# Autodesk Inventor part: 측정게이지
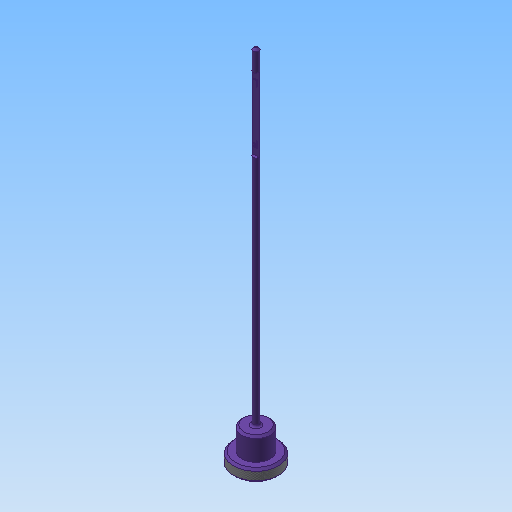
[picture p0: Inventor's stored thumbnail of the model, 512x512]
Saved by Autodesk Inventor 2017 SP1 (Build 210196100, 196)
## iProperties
Created: 2017-05
Part Number: 측정게이지
Material: 스테인리스강
Document SubType Name: Modeling
Designer: mduedu
Density: 8.08 g/cm^3
Mass: 39.5088 g
Surface Area: 29.9761 cm^2
Volume: 4.8897 cm^3
Appearance: 보라색
Author: mduedu
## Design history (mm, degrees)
sketch "스케치1"
  geometry: C1 r 11 at (0, 0); 1 further point
  constraints: 1 centre point, 1 coincident
  dimensions: "d0" = 22 diameter of C1
extrude "돌출1" new body sketch "스케치1" distance "d2" = 6; taper "d3" = 0 deg
sketch "스케치2"
  geometry: C1 r 7 at (0, 0); 1 further point
  constraints: 1 centre point, 1 coincident
  dimensions: "d4" = 14 diameter of C1
extrude "돌출2" join sketch "스케치2" distance "d5" = 11; taper "d6" = 0 deg
sketch "스케치3"
  geometry: C1 r 1.5 at (0, 0); 1 further point
  constraints: 1 centre point, 1 coincident
  dimensions: "d7" = 3 diameter of C1
extrude "돌출3" join sketch "스케치3" distance "d8" = 160; taper "d9" = 0 deg
fillet "모깎기1" dims "d10" = 1
chamfer "모따기1" distance "d11" = 1; stored, may be unused: second distance "d12" = 2, angle "d13" = 45 deg
sketch "스케치4"
  geometry: L1 (16, 7)-(17, 6) reference; L2 (6, 7)-(16, 7) reference; L3 (16, -7)-(6, -7) reference; L4 (17, -6)-(16, -7) reference; L5 (17, 6)-(17, 2.5) reference; L6 (18, 1.5)-(176, 1.5) reference; L7 (176, 1.5)-(177, 0.5) reference; L8 (177, 0.5)-(177, -0.5) reference; L9 (177, -0.5)-(176, -1.5) reference; L10 (176, -1.5)-(18, -1.5) reference; L11 (17, -2.5)-(17, -6) reference; L12 (177, 0)-(0, 0); L13 (167, 0)-(131, 0); L14 (131, 0)-(131, 1.5); L15 (131, 1.5)-(167, 1.5); L16 (167, 1.5)-(167, 0); L17 (0, 11)-(6, 11) reference; L18 (6, 11)-(6, 7) reference; L19 (6, -7)-(6, -11) reference; L20 (6, -11)-(0, -11) reference; L21 (0, -11)-(0, 11) reference; A1 r 1 centre (18, 2.5) between (17, 2.5) and (18, 1.5) reference; A2 r 1 centre (18, -2.5) between (18, -1.5) and (17, -2.5) reference
  constraints: 10 end point, 2 parallel, 2 point on line, 1 horizontal, 1 midpoint, 1 perpendicular
  dimensions: "d14" = 10 distance from line of L16 L7.end; "d15" = 36 distance between parallel lines of L14 L16
extrude "돌출4" cut sketch "스케치4" stored distance "d16" = 160; taper "d17" = 0 deg
sketch "스케치5"
  geometry: L1 (0, 0)-(3, 0) reference; L2 (3, 36)-(0, 36) reference; L3 (1.5, 0)-(1.5, 36); 3 further points
  constraints: 2 end point, 2 midpoint, 2 point on line, 2 other
  dimensions: "d18" = 5 distance from line of point (1.5, 5) L1; "d19" = 5 distance from line of point (1.5, 31) L2
feature "엠보싱1" sketch "스케치5" dims "d20" = 0.3, "d21" = 0
chamfer "모따기2" distance "d32" = 1; stored, may be unused: second distance "d33" = 2, angle "d34" = 45 deg
node "솔리드1"
node "절단 모서리 투영1"
